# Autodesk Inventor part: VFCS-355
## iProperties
Author: Ole Germer
Shininess: 60.0
PropertySet Name: _Private Model Information
Created: 2001-03
Part Number: VFCS-355
Material: Steel, High Strength Low Alloy
Document SubType Name: Modeling
Designer: Ole Germer
Description: Browing Flange Cartridge, 3 7/16
Control State: 0
Master: False
Checked Out: False
PropertySet Name: Design Tracking Control
Density: 7.84
Volumn: 2471.260463976183
Area: 2552.342196881437
PropertySet Name: Model Information
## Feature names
1. Revolution1
2. Hole1
3. Circular Pattern1
4. Extrusion1
5. Extrusion2
6. Revolution3
7. Extrusion4
8. Circular Pattern3
9. Fillet1
10. Hole3
11. Circular Pattern4
12. Revolution4
